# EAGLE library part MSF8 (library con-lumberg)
MSF CONNECTOR
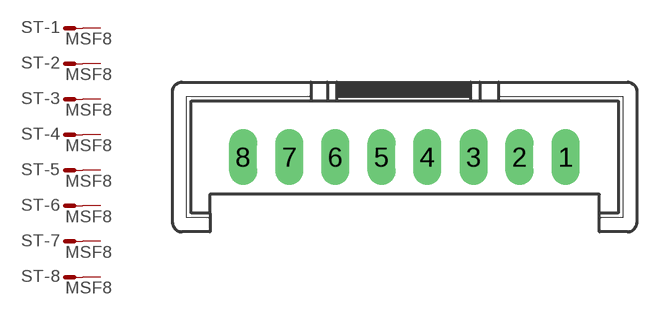
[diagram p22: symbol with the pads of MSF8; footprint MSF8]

Designator prefix ST; gates -1=M -2=M -3=M -4=M -5=M -6=M -7=M -8=M

## MSF8 (OC_FARNELL: unknown; OC_NEWARK: unknown)  [MSF8]
1  -1:S  pas
2  -2:S  pas
3  -3:S  pas
4  -4:S  pas
5  -5:S  pas
6  -6:S  pas
7  -7:S  pas
8  -8:S  pas

## Footprint MSF8 (pad centres in mm)
MSF CONNECTOR
drill 1.016 long: 1 8.763,-2.54; 2 6.248,-2.54; 3 3.759,-2.54; 4 1.245,-2.54; 5 -1.245,-2.54; 6 -3.759,-2.54; 7 -6.248,-2.54; 8 -8.763,-2.54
